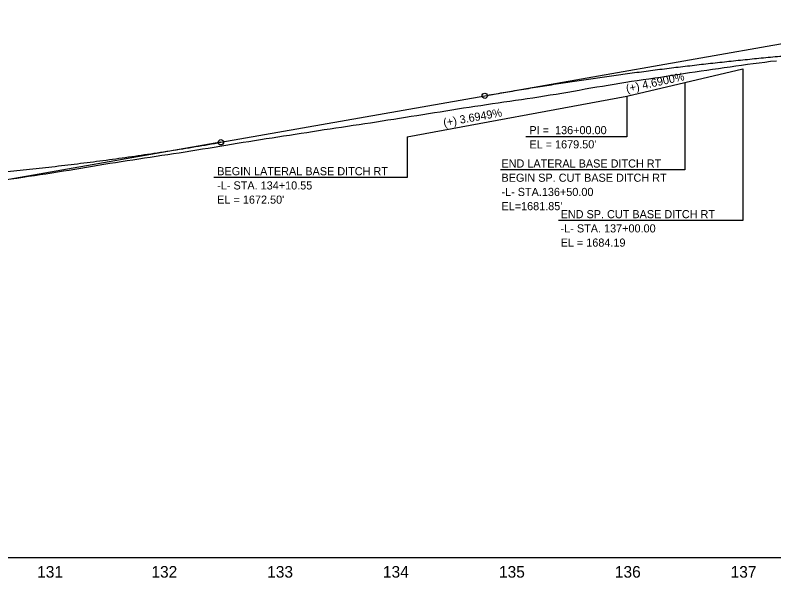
# Model space of a CAD drawing. Extents: x 498575 to 532350, y 405181 to 484585.
# Drawn here: x 517892 to 518546, y 483216 to 483701 of the extents above; entities that cross this region are included whole.
import ezdxf

# ---------------------------------------------------------------- set-up
doc = ezdxf.new("R2010")
doc.units = 0
for name, color, linetype in [('Exist Profile Cell', 7, 'Continuous'), ('Exist Vertical Profile Ground Line', 7, 'Continuous'), ('Exist Vertical Profile Horizontal Axis Label Major', 7, 'Continuous'), ('Prop Vertical Profile Curve Label', 7, 'Continuous'), ('Prop Vertical Profile Ditch Grade Right', 7, 'Continuous'), ('Prop Vertical Profile Ditch Grade Right Label', 7, 'Continuous'), ('Prop Vertical Profile Grade', 7, 'Continuous'), ('Prop VPI Label', 7, 'Continuous')]:
    doc.layers.add(name, color=color, linetype=linetype)

msp = doc.modelspace()

# ---------------------------------------------------------------- linework, layer by layer
at = {"layer": 'Exist Profile Cell'}
msp.add_line((505856.74, 483233.71), (526056.74, 483233.71), dxfattribs=at)
at = {"layer": 'Exist Vertical Profile Ground Line'}
for points in [[(518313.15, 483626.22), (518318.15, 483626.97), (518323.15, 483627.68), (518328.15, 483628.43), (518333.15, 483629.13), (518338.15, 483629.88), (518343.15, 483630.64), (518348.15, 483631.41), (518353.15, 483632.2), (518358.15, 483633.02), (518363.15, 483633.88), (518368.15, 483634.74), (518373.15, 483635.61), (518378.15, 483636.49), (518383.15, 483637.38), (518388.15, 483638.27), (518393.15, 483639.09), (518398.15, 483639.93), (518403.15, 483640.75), (518408.15, 483641.58), (518413.15, 483642.38), (518418.15, 483643.19), (518423.15, 483643.98), (518428.15, 483644.75), (518433.15, 483645.5), (518438.15, 483646.25), (518443.15, 483646.96), (518448.15, 483647.7), (518453.15, 483648.45), (518458.15, 483649.19), (518463.15, 483649.98), (518468.15, 483650.74), (518473.15, 483651.46), (518478.15, 483652.21), (518483.15, 483652.94), (518488.15, 483653.67), (518493.15, 483654.42), (518498.15, 483655.16), (518503.15, 483655.89), (518508.15, 483656.6), (518513.15, 483657.29), (518518.15, 483657.98), (518523.15, 483658.66), (518528.15, 483659.32), (518533.15, 483659.97), (518538.15, 483660.6), (518543.15, 483661.23), (518548.15, 483661.77)], [(517888.15, 483559.85), (517893.15, 483560.6), (517898.15, 483561.38), (517903.15, 483562.14), (517908.15, 483562.87), (517913.15, 483563.64), (517918.15, 483564.39), (517923.15, 483565.15), (517928.15, 483565.95), (517933.15, 483566.75), (517938.15, 483567.55), (517943.15, 483568.36), (517948.15, 483569.18), (517953.15, 483570), (517958.15, 483570.84), (517963.15, 483571.68), (517968.15, 483572.51), (517973.15, 483573.31), (517978.15, 483574.13), (517983.15, 483574.9), (517988.15, 483575.65), (517993.15, 483576.42), (517998.15, 483577.2), (518003.15, 483577.95), (518008.15, 483578.74), (518013.15, 483579.5), (518018.15, 483580.23), (518023.15, 483580.99), (518028.15, 483581.73), (518033.15, 483582.49), (518038.15, 483583.28), (518043.15, 483584.08), (518048.15, 483584.85), (518053.15, 483585.67), (518058.15, 483586.47), (518063.15, 483587.27), (518068.15, 483588.08), (518073.15, 483588.92), (518078.15, 483589.74), (518083.15, 483590.57), (518088.15, 483591.4), (518093.15, 483592.2), (518098.15, 483592.99), (518103.15, 483593.8), (518108.15, 483594.59), (518113.15, 483595.38), (518118.15, 483596.13), (518123.15, 483596.92), (518128.15, 483597.69), (518133.15, 483598.45), (518138.15, 483599.22), (518143.15, 483599.99), (518148.15, 483600.77), (518153.15, 483601.56), (518158.15, 483602.33), (518163.15, 483603.09), (518168.15, 483603.87), (518173.15, 483604.59), (518178.15, 483605.33), (518183.15, 483606.08), (518188.15, 483606.83), (518193.15, 483607.6), (518198.15, 483608.33), (518203.15, 483609.11), (518208.15, 483609.9), (518213.15, 483610.67), (518218.15, 483611.47), (518223.15, 483612.25), (518228.15, 483613.09), (518233.15, 483613.84), (518238.15, 483614.64), (518243.15, 483615.45), (518248.15, 483616.22), (518253.15, 483617.01), (518258.15, 483617.82), (518263.15, 483618.65), (518268.15, 483619.42), (518273.15, 483620.24), (518278.15, 483621.03), (518283.15, 483621.8), (518288.15, 483622.54), (518293.15, 483623.25), (518298.15, 483624.06), (518303.15, 483624.78), (518308.15, 483625.49), (518313.15, 483626.22)]]:
    msp.add_lwpolyline(points, dxfattribs=at)
at = {"layer": 'Prop Vertical Profile Curve Label'}
for centre in [(518296.58, 483631.5), (518069.08, 483591.46)]:
    msp.add_circle(centre, 2.25, dxfattribs=at)
at = {"layer": 'Prop Vertical Profile Ditch Grade Right'}
msp.add_lwpolyline([(518229.63, 483596.21), (518419.08, 483631.21), (518519.08, 483654.66), (518519.08, 483654.66)], dxfattribs=at)
at = {"layer": 'Prop Vertical Profile Ditch Grade Right Label'}
for p, q in [((518519.08, 483654.66), (518519.08, 483524.14)), ((518469.08, 483642.94), (518469.08, 483567.84)), ((518419.08, 483631.21), (518419.08, 483596.1)), ((518229.63, 483596.21), (518229.63, 483561.1)), ((518419.08, 483596.1), (518332.11, 483596.1)), ((518469.08, 483567.84), (518310.21, 483567.84)), ((518229.63, 483561.1), (518062.95, 483561.1)), ((518519.08, 483524.14), (518360.21, 483524.14))]:
    msp.add_line(p, q, dxfattribs=at)
at = {"layer": 'Prop Vertical Profile Grade'}
msp.add_line((518069.08, 483591.46), (518296.58, 483631.5), dxfattribs=at)
for points in [[(518296.58, 483631.5), (518312.48, 483634.26), (518328.38, 483636.93), (518344.28, 483639.52), (518360.18, 483642.03), (518376.08, 483644.45), (518391.98, 483646.79), (518407.88, 483649.05), (518423.78, 483651.22), (518439.68, 483653.31), (518455.58, 483655.32), (518471.48, 483657.24), (518487.38, 483659.08), (518503.28, 483660.84), (518519.18, 483662.51), (518535.08, 483664.1), (518550.98, 483665.61), (518566.88, 483667.03), (518582.78, 483668.37), (518598.68, 483669.63), (518614.58, 483670.8), (518630.48, 483671.89), (518646.38, 483672.89), (518662.28, 483673.82), (518678.18, 483674.66), (518694.08, 483675.41), (518709.98, 483676.09), (518725.88, 483676.68), (518741.78, 483677.18), (518757.68, 483677.6), (518773.58, 483677.94), (518789.48, 483678.2), (518805.38, 483678.37), (518821.28, 483678.46), (518837.18, 483678.47), (518853.08, 483678.39), (518868.98, 483678.23), (518884.88, 483677.99), (518900.78, 483677.66), (518916.68, 483677.25), (518932.58, 483676.75), (518948.48, 483676.18), (518964.38, 483675.52), (518980.28, 483674.77), (518996.18, 483673.94), (519012.08, 483673.03), (519027.98, 483672.04), (519043.88, 483670.96), (519059.78, 483669.8), (519075.68, 483668.56), (519091.58, 483667.23)], [(516969.08, 483658.97), (516991.08, 483652.5), (517013.08, 483646.24), (517035.08, 483640.19), (517057.08, 483634.35), (517079.08, 483628.72), (517101.08, 483623.29), (517123.08, 483618.08), (517145.08, 483613.07), (517167.08, 483608.28), (517189.08, 483603.69), (517211.08, 483599.31), (517233.08, 483595.14), (517255.08, 483591.18), (517277.08, 483587.43), (517299.08, 483583.88), (517321.08, 483580.55), (517343.08, 483577.42), (517365.08, 483574.51), (517387.08, 483571.8), (517409.08, 483569.3), (517431.08, 483567.01), (517453.08, 483564.93), (517475.08, 483563.06), (517497.08, 483561.39), (517519.08, 483559.94), (517541.08, 483558.69), (517563.08, 483557.66), (517585.08, 483556.83), (517607.08, 483556.21), (517629.08, 483555.8), (517651.08, 483555.6), (517673.08, 483555.61), (517695.08, 483555.82), (517717.08, 483556.25), (517739.08, 483556.88), (517761.08, 483557.72), (517783.08, 483558.78), (517805.08, 483560.04), (517827.08, 483561.51), (517849.08, 483563.19), (517871.08, 483565.07), (517893.08, 483567.17), (517915.08, 483569.48), (517937.08, 483571.99), (517959.08, 483574.71), (517981.08, 483577.64), (518003.08, 483580.79), (518025.08, 483584.14), (518047.08, 483587.69), (518069.08, 483591.46)]]:
    msp.add_spline(points, degree=3, dxfattribs=at)
at = {"layer": 'Prop VPI Label'}
for p, q in [((518296.58, 483631.5), (518691.37, 483700.99)), ((518069.08, 483591.46), (517521.78, 483495.14))]:
    msp.add_line(p, q, dxfattribs=at)

# ---------------------------------------------------------------- texts
at = {"layer": 'Exist Vertical Profile Horizontal Axis Label Major'}
for s, p in [('131', (517910.54, 483216.21)), ('131', (517910.55, 483216.21)), ('132', (518009.09, 483216.21)), ('132', (518009.1, 483216.21)), ('133', (518108.93, 483216.21)), ('133', (518108.93, 483216.21)), ('134', (518208.77, 483216.21)), ('134', (518208.77, 483216.21)), ('135', (518308.87, 483216.21)), ('135', (518308.86, 483216.21)), ('136', (518408.8, 483216.21)), ('136', (518408.81, 483216.21)), ('137', (518508.66, 483216.21)), ('137', (518508.66, 483216.21))]:
    msp.add_text(s, height=10, dxfattribs=at).set_placement(p)
at = {"layer": 'Prop Vertical Profile Ditch Grade Right Label'}
for s, rotation, p in [('(+) 4.6900%', 12.24917, (518419.2, 483634.15)), ('(+) 3.6949%', 10.19776, (518261.5, 483604.83)), ('PI =  136+00.00', 360, (518335.11, 483598.42)), ("EL = 1679.50'", 360, (518335.11, 483586.17)), ('END LATERAL BASE DITCH RT', 360, (518310.99, 483569.66)), ('BEGIN LATERAL BASE DITCH RT', 360, (518065.88, 483563.01)), ('BEGIN SP. CUT BASE DITCH RT', 360, (518310.99, 483557.41)), ('-L- STA. 134+10.55', 360, (518065.88, 483550.76)), ('-L- STA.136+50.00', 360, (518310.99, 483545.16)), ("EL = 1672.50'", 360, (518065.88, 483538.51)), ("EL=1681.85'", 360, (518310.99, 483532.91)), ('END SP. CUT BASE DITCH RT', 360, (518362.03, 483525.99)), ('-L- STA. 137+00.00', 360, (518362.03, 483513.74)), ('EL = 1684.19', 360, (518362.03, 483501.49))]:
    msp.add_text(s, height=7, rotation=rotation, dxfattribs=at).set_placement(p)

doc.saveas('drawing.dxf')
